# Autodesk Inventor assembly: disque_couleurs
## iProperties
Created: 2011-01
Part Number: disque_couleurs
Document SubType Name: Assembly
Designer: eric
Mass: 10.4757 g
Surface Area: 211.41 cm^2
Volume: 10.4757 cm^3
Density: 1 g/cm^3
Norme de conversion: IGES 5.3
Nom du fichier: No Iges File Name specified
Préprocesseur: Autodesk Inventor 2011
Postprocesseur: Build: 342, Release: 2008 SP3 - Date: Tue 05/27/2008
Unités envoyées: MM
Incertitude: 0.01
Author: eric
